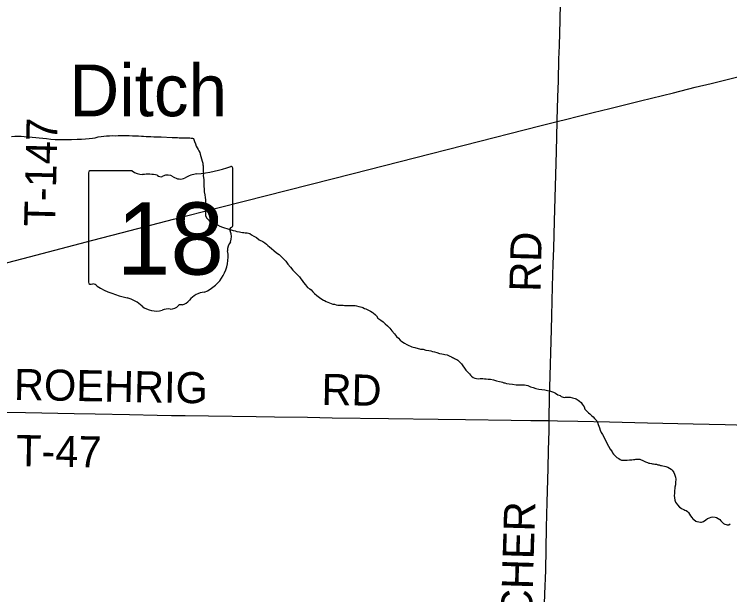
# Model space of a CAD drawing. Extents: x 2.1 to 73.9, y 4 to 26.
# Drawn here: x 47.176 to 47.83, y 23.154 to 23.685 of the extents above; entities that cross this region are included whole.
import ezdxf

# ---------------------------------------------------------------- set-up
doc = ezdxf.new("R2010")
doc.units = 0
for name, color, linetype in [('GM_X_Minor_River', 7, 'Continuous'), ('GM_X_Minor_River_Text', 7, 'Continuous'), ('GM_X_State_Location', 7, 'Continuous'), ('GM_X_State_Route', 7, 'Continuous'), ('GM_X_State_Shield', 7, 'Continuous'), ('GM_X_Township_Road', 7, 'Continuous'), ('GM_X_Township_Road_Text', 7, 'Continuous')]:
    doc.layers.add(name, color=color, linetype=linetype)

msp = doc.modelspace()

# ---------------------------------------------------------------- linework, layer by layer
at = {"layer": 'GM_X_Minor_River'}
for points in [[(47.17357, 23.57348), (47.17661, 23.57378), (47.17946, 23.57371), (47.18231, 23.57364), (47.18515, 23.57337), (47.18837, 23.5731), (47.19254, 23.5728), (47.19576, 23.57253), (47.19898, 23.57207), (47.2022, 23.5718), (47.20562, 23.57152), (47.20959, 23.57104), (47.21338, 23.57075), (47.21718, 23.57066), (47.22098, 23.57075), (47.22459, 23.57066), (47.22839, 23.57075), (47.23352, 23.57081), (47.23751, 23.57109), (47.24131, 23.57118), (47.24455, 23.57167), (47.2476, 23.57197), (47.25008, 23.57229), (47.25276, 23.57298), (47.25543, 23.57348), (47.2579, 23.5738), (47.26057, 23.57392), (47.26323, 23.57404), (47.26551, 23.57417), (47.26855, 23.5741), (47.27102, 23.57422), (47.2733, 23.57416), (47.27577, 23.57429), (47.27824, 23.57423), (47.28108, 23.57416), (47.28412, 23.57408), (47.28716, 23.574), (47.28982, 23.57393), (47.29228, 23.57368), (47.29437, 23.57363), (47.29664, 23.57338), (47.29873, 23.57333), (47.301, 23.57327), (47.30366, 23.5732), (47.30689, 23.57312), (47.31031, 23.57303), (47.32036, 23.57259), (47.32302, 23.57252), (47.3253, 23.57246), (47.327, 23.57223), (47.32928, 23.57217), (47.33175, 23.5723), (47.33403, 23.57224), (47.33517, 23.57221), (47.33668, 23.57217), (47.33782, 23.57195), (47.33895, 23.57173), (47.3399, 23.57171), (47.34078, 23.56884), (47.34167, 23.56654), (47.34238, 23.56443), (47.34329, 23.56289), (47.3442, 23.56154), (47.34493, 23.56038), (47.34584, 23.55865), (47.34619, 23.55731), (47.3467, 23.55502), (47.34741, 23.55291), (47.34792, 23.55081), (47.34844, 23.5489), (47.3486, 23.54757), (47.34895, 23.54642), (47.34892, 23.54528), (47.34889, 23.54395), (47.34885, 23.54262), (47.34882, 23.54111), (47.34897, 23.53958), (47.34892, 23.53769), (47.34939, 23.53369), (47.34936, 23.53236), (47.34931, 23.53046), (47.34944, 23.52799), (47.34975, 23.52532), (47.34987, 23.52266), (47.35038, 23.52018), (47.3507, 23.51771), (47.35083, 23.51561), (47.35095, 23.51276), (47.35089, 23.5103), (47.35082, 23.50764), (47.35077, 23.50574), (47.35092, 23.50384), (47.35088, 23.50251), (47.35084, 23.501), (47.3523, 23.49868), (47.35435, 23.49673), (47.35565, 23.49575), (47.35677, 23.49515), (47.35977, 23.49336), (47.36184, 23.49255), (47.36409, 23.49136)], [(47.36409, 23.49136), (47.36635, 23.49054), (47.36841, 23.48973), (47.3703, 23.4893), (47.37633, 23.48744), (47.37803, 23.48701), (47.37973, 23.48659), (47.382, 23.48615), (47.38332, 23.48593), (47.38465, 23.48571), (47.38597, 23.48548), (47.3873, 23.48545), (47.389, 23.48521), (47.39033, 23.48499), (47.39146, 23.48458), (47.39314, 23.48359), (47.3952, 23.4824), (47.39744, 23.48101), (47.40005, 23.47886), (47.40343, 23.47725), (47.4053, 23.47607), (47.4066, 23.47489), (47.4079, 23.47372), (47.40939, 23.47255), (47.41124, 23.47098), (47.41348, 23.46902), (47.4159, 23.46706), (47.41814, 23.46549), (47.42018, 23.46373), (47.42203, 23.46178), (47.42425, 23.45926), (47.42627, 23.45655), (47.42867, 23.45383), (47.43088, 23.4513), (47.43291, 23.44897), (47.43514, 23.44683), (47.4368, 23.44508), (47.43809, 23.44334), (47.43937, 23.44159), (47.44066, 23.43985), (47.44232, 23.43791), (47.44416, 23.4354), (47.4464, 23.43401), (47.44752, 23.43322), (47.44919, 23.43147), (47.45067, 23.42991), (47.45271, 23.42796), (47.45513, 23.42619), (47.45737, 23.42462), (47.45887, 23.42382), (47.45981, 23.42342), (47.4613, 23.42243), (47.46733, 23.42019), (47.46884, 23.41996), (47.47054, 23.41954), (47.47205, 23.41931), (47.47338, 23.41928), (47.47432, 23.41906), (47.47566, 23.41922), (47.4768, 23.41919), (47.47793, 23.41897), (47.4804, 23.41891), (47.48249, 23.41885), (47.48438, 23.41881), (47.48571, 23.41877), (47.48685, 23.41874), (47.4878, 23.41872), (47.48912, 23.41849), (47.49101, 23.41807), (47.49252, 23.41765), (47.49384, 23.41724), (47.49479, 23.41702), (47.49628, 23.41622), (47.49741, 23.41582), (47.49873, 23.41521), (47.50042, 23.41441), (47.50192, 23.41361), (47.50342, 23.41282), (47.50435, 23.41203), (47.50621, 23.41047), (47.50713, 23.4093), (47.5086, 23.40737), (47.51121, 23.40559), (47.51326, 23.40383), (47.5153, 23.40207), (47.51734, 23.40012), (47.51938, 23.39817), (47.52141, 23.39565), (47.52362, 23.39294), (47.52565, 23.39061), (47.52731, 23.38886), (47.52879, 23.3873), (47.53047, 23.38593), (47.5329, 23.38435), (47.53496, 23.38315), (47.53683, 23.38216), (47.53834, 23.38174), (47.53966, 23.38114), (47.54078, 23.38073), (47.54229, 23.38031), (47.54739, 23.37904)], [(47.54739, 23.37904), (47.54985, 23.37879), (47.5523, 23.37816), (47.55514, 23.3777), (47.55684, 23.37728), (47.55835, 23.37686), (47.56024, 23.37644), (47.56231, 23.37581), (47.56476, 23.37499), (47.56703, 23.37455), (47.56854, 23.37433), (47.56987, 23.3741), (47.57176, 23.37368), (47.57307, 23.37307), (47.57438, 23.37247), (47.5757, 23.37206), (47.57683, 23.37146), (47.57777, 23.37105), (47.5787, 23.37046), (47.57983, 23.36986), (47.58076, 23.36946), (47.5817, 23.36887), (47.58263, 23.36808), (47.58356, 23.36711), (47.58485, 23.36556), (47.58613, 23.36363), (47.5876, 23.36169), (47.58907, 23.35975), (47.59036, 23.3582), (47.59147, 23.35723), (47.5924, 23.35625), (47.59313, 23.35528), (47.59425, 23.35431), (47.59555, 23.35313), (47.59705, 23.35234), (47.59856, 23.35211), (47.60046, 23.35187), (47.60217, 23.35202), (47.60445, 23.35215), (47.60616, 23.35192), (47.60748, 23.35169), (47.60938, 23.35164), (47.61165, 23.3514), (47.61411, 23.35095), (47.61694, 23.35012), (47.61958, 23.34949), (47.62128, 23.34906), (47.62241, 23.34866), (47.62373, 23.34824), (47.62467, 23.34803), (47.62618, 23.34761), (47.62864, 23.34717), (47.63167, 23.3469), (47.63489, 23.34644), (47.63792, 23.34636), (47.64058, 23.3463), (47.64248, 23.34625), (47.64399, 23.34602), (47.6455, 23.3456), (47.64813, 23.34458), (47.65039, 23.34377), (47.65284, 23.34295), (47.65567, 23.3423), (47.66116, 23.3416), (47.66362, 23.34115), (47.66551, 23.34073), (47.66909, 23.33969), (47.67097, 23.33869), (47.67302, 23.33731), (47.67509, 23.3365), (47.67602, 23.33571), (47.67696, 23.33531), (47.6779, 23.33509), (47.67904, 23.33488), (47.68018, 23.33504), (47.68132, 23.33501), (47.68436, 23.33493), (47.68643, 23.33431), (47.68756, 23.33409), (47.68888, 23.33368), (47.68983, 23.33346), (47.6917, 23.33228), (47.69281, 23.3313), (47.6943, 23.33012), (47.69541, 23.32876), (47.69632, 23.32741), (47.69705, 23.32625), (47.69776, 23.32415), (47.69906, 23.32279), (47.70017, 23.32162), (47.70109, 23.32065), (47.70221, 23.31986), (47.70333, 23.31888), (47.70426, 23.3181), (47.70537, 23.31693), (47.70647, 23.31557), (47.70777, 23.3144), (47.7087, 23.31343), (47.70924, 23.31227), (47.70994, 23.31017), (47.71066, 23.30844)], [(47.71066, 23.30844), (47.71119, 23.30691), (47.7119, 23.30499), (47.7128, 23.30288), (47.71389, 23.30095), (47.71498, 23.29884), (47.71606, 23.29653), (47.71734, 23.2946), (47.71824, 23.29249), (47.71932, 23.29037), (47.72077, 23.28749), (47.72207, 23.28612), (47.72261, 23.28516), (47.72316, 23.2842), (47.72408, 23.28304), (47.72536, 23.2813), (47.72685, 23.27993), (47.72872, 23.27893), (47.73003, 23.27795), (47.73134, 23.27735), (47.73648, 23.27759), (47.73857, 23.27773), (47.74085, 23.27786), (47.74237, 23.27802), (47.74333, 23.27818), (47.74447, 23.27834), (47.74599, 23.2783), (47.74694, 23.27847), (47.74789, 23.27845), (47.74921, 23.27784), (47.75015, 23.27744), (47.75127, 23.27684), (47.75315, 23.27603), (47.75503, 23.27523), (47.75635, 23.27481), (47.75729, 23.2746), (47.75862, 23.27437), (47.75956, 23.27416), (47.76051, 23.27414), (47.76183, 23.27391), (47.76316, 23.27369), (47.76448, 23.27328), (47.76561, 23.27306), (47.76693, 23.27265), (47.76788, 23.27262), (47.7692, 23.2724), (47.77052, 23.27198), (47.77184, 23.27157), (47.77353, 23.27096), (47.77522, 23.27016), (47.77672, 23.26917), (47.77765, 23.26839), (47.77838, 23.26723), (47.77911, 23.26626), (47.77983, 23.26472), (47.78, 23.26358), (47.78052, 23.26186), (47.78085, 23.25995), (47.78078, 23.2571), (47.78054, 23.25483), (47.7801, 23.25275), (47.77988, 23.25124), (47.77966, 23.25011), (47.77962, 23.24878), (47.77958, 23.24688), (47.77953, 23.24517), (47.78, 23.24098), (47.78071, 23.23907), (47.78236, 23.23656), (47.78439, 23.23442), (47.78589, 23.23343), (47.78683, 23.23303), (47.78832, 23.23223), (47.78926, 23.23182), (47.79039, 23.23142), (47.79151, 23.23044), (47.79244, 23.22966), (47.79353, 23.22792), (47.79426, 23.22657), (47.79555, 23.22502), (47.79647, 23.22367), (47.7974, 23.22307), (47.79927, 23.2217), (47.80021, 23.22148), (47.8021, 23.22106), (47.80361, 23.22064), (47.80456, 23.22061), (47.80609, 23.22133), (47.80823, 23.22299), (47.80996, 23.22408), (47.81169, 23.2248), (47.81322, 23.22533), (47.81475, 23.22567), (47.81683, 23.22543), (47.81815, 23.22502), (47.81965, 23.22403), (47.82115, 23.22323), (47.82207, 23.22207), (47.82317, 23.22071), (47.82447, 23.21954), (47.8256, 23.21894)], [(47.8256, 23.21894), (47.82692, 23.21853), (47.82786, 23.21831), (47.82938, 23.21846), (47.83073, 23.21919)]]:
    msp.add_lwpolyline(points, dxfattribs=at)
at = {"layer": 'GM_X_State_Route'}
for points in [[(47.67253, 23.58703), (47.68142, 23.58928), (47.69077, 23.59162), (47.70525, 23.59521), (47.72063, 23.59905), (47.7487, 23.60595), (47.77887, 23.61346), (47.79877, 23.61839), (47.81326, 23.62193), (47.8413, 23.62897), (47.88412, 23.63968), (47.9155, 23.64743), (47.95867, 23.65798), (47.99695, 23.66765), (48.01205, 23.67132), (48.02864, 23.67544), (48.03859, 23.67792), (48.06363, 23.68416), (48.07726, 23.68735)], [(47.16323, 23.45636), (47.19003, 23.46337), (47.24807, 23.47852), (47.28204, 23.48746), (47.32172, 23.4979), (47.36211, 23.50809), (47.38622, 23.51417), (47.48591, 23.53959), (47.54195, 23.5538), (47.58745, 23.56532), (47.65671, 23.58304), (47.67253, 23.58703)]]:
    msp.add_lwpolyline(points, dxfattribs=at)
at = {"layer": 'GM_X_State_Shield'}
for p, q in [((47.24395, 23.54014), (47.24395, 23.44008)), ((47.28386, 23.54186), (47.24525, 23.54186)), ((47.37579, 23.492), (47.37579, 23.54434)), ((47.37577, 23.49201), (47.37579, 23.492))]:
    msp.add_line(p, q, dxfattribs=at)
for centre, radius, start, end in [((47.32883, 23.67827), 0.13981, 275.84447, 288.90645), ((47.37432, 23.54455), 0.00147, 351.86209, 97.738), ((47.24546, 23.54035), 0.00153, 98.1301, 188.1301), ((47.29305, 23.55347), 0.01481, 231.61951, 271.11188), ((47.34666, 23.5113), 0.02813, 97.34618, 120.76885), ((47.29796, 23.48568), 0.05318, 80.48669, 94.98827), ((47.31004, 23.54087), 0.00427, 219.79206, 297.10237), ((47.31631, 23.5293), 0.00889, 54.46668, 119.14113), ((47.32778, 23.54517), 0.01069, 233.85621, 294.82819), ((47.37545, 23.48815), 0.00227, 107.94398, 210.33697), ((47.361, 23.48154), 0.01363, 340.03296, 23.64957), ((47.37422, 23.49179), 0.00157, 289.60381, 7.73413), ((47.38104, 23.47009), 0.00992, 136.8065, 186.92959), ((47.33666, 23.46343), 0.03497, 292.30889, 8.98584), ((47.24548, 23.43986), 0.00154, 171.95839, 258.30661), ((47.24571, 23.45009), 0.01176, 267.33899, 280.60386), ((47.24812, 23.4343), 0.00424, 29.74838, 93.27175), ((47.30165, 23.5242), 0.10096, 240.41292, 257.1985), ((47.3514, 23.41198), 0.01915, 94.40312, 142.57675), ((47.27155, 23.39512), 0.03159, 47.18416, 75.83597), ((47.32714, 23.43038), 0.0113, 282.87319, 323.27711), ((47.30571, 23.43381), 0.02004, 230.70037, 286.29184), ((47.31729, 23.39921), 0.01647, 85.69512, 111.20995), ((47.31876, 23.42631), 0.01068, 268.77702, 315.54927), ((47.32842, 23.41662), 0.00301, 65.75173, 132.64842)]:
    msp.add_arc(centre, radius, start, end, dxfattribs=at)
at = {"layer": 'GM_X_Township_Road'}
for points in [[(47.67253, 23.58703), (47.67256, 23.58821), (47.67309, 23.60934), (47.67352, 23.62426), (47.67412, 23.64415), (47.67449, 23.65626), (47.67517, 23.67988), (47.67557, 23.69542), (47.67604, 23.71064), (47.67664, 23.7352), (47.67721, 23.75882), (47.67788, 23.78834), (47.67823, 23.80077), (47.67853, 23.81504)], [(47.6652, 23.31356), (47.66555, 23.3365), (47.66572, 23.34395), (47.66723, 23.39678), (47.66758, 23.40952), (47.66828, 23.43625), (47.66886, 23.45707), (47.66926, 23.47105), (47.67, 23.49591), (47.67178, 23.55962), (47.67253, 23.58703)], [(47.03459, 23.32485), (47.04417, 23.32468), (47.06964, 23.32379), (47.09543, 23.32313), (47.12992, 23.32215), (47.15105, 23.32161), (47.16596, 23.32138), (47.18647, 23.32095), (47.23091, 23.32009), (47.25018, 23.3197), (47.28156, 23.31915), (47.30673, 23.31859), (47.31978, 23.31837), (47.33224, 23.31822)], [(47.33224, 23.31822), (47.35366, 23.31795), (47.39717, 23.31735), (47.41395, 23.3171), (47.4441, 23.3167), (47.46678, 23.31627), (47.51837, 23.31556), (47.56375, 23.31487), (47.58861, 23.31459), (47.63026, 23.31411), (47.64828, 23.31386), (47.6652, 23.31356)], [(47.65556, 22.97344), (47.65572, 22.97816), (47.65674, 23.00895), (47.65729, 23.02884), (47.65796, 23.04716), (47.65876, 23.07359), (47.65976, 23.11367), (47.66057, 23.13635), (47.66121, 23.15531), (47.66198, 23.17643), (47.66275, 23.21591), (47.66333, 23.2389), (47.66419, 23.26967), (47.66463, 23.28645), (47.66506, 23.30417), (47.6652, 23.31356)], [(47.6652, 23.31356), (47.67283, 23.31343), (47.69148, 23.31321), (47.72038, 23.3125), (47.75517, 23.31148), (47.79681, 23.31061), (47.82601, 23.30992), (47.85708, 23.30916), (47.89405, 23.30811), (47.90896, 23.30777), (47.95029, 23.30664), (48.01492, 23.30515), (48.06495, 23.30394), (48.08484, 23.30361), (48.11342, 23.30283), (48.13859, 23.30224), (48.15174, 23.30191)]]:
    msp.add_lwpolyline(points, dxfattribs=at)

# ---------------------------------------------------------------- texts
at = {"layer": 'GM_X_Minor_River_Text'}
msp.add_text('Ditch', height=0.047373, rotation=0.03997, dxfattribs=at).set_placement((47.22633, 23.59182))
at = {"layer": 'GM_X_State_Location'}
for s in ['s', 'r']:
    msp.add_text(s, height=0.0000947, dxfattribs=at).set_placement((47.30838, 23.48345))
msp.add_text('18', height=0.0000947, rotation=0.00001, dxfattribs=at).set_placement((47.28454, 23.47656))
at = {"layer": 'GM_X_State_Shield'}
msp.add_text('18', height=0.065918, dxfattribs=at).set_placement((47.26981, 23.44713))
at = {"layer": 'GM_X_Township_Road_Text'}
for s, rotation, p in [('T-147', 88.60854, (47.21342, 23.49079)), ('RD', 88.51776, (47.65712, 23.43111)), ('ROEHRIG', 358.92351, (47.1756, 23.3326)), ('RD', 359.01679, (47.45682, 23.328)), ('T-47', 358.94455, (47.17756, 23.27213)), ('ASHPACHER', 88.28513, (47.64545, 23.00297))]:
    msp.add_text(s, height=0.028409, rotation=rotation, dxfattribs=at).set_placement(p)

doc.saveas('drawing.dxf')
